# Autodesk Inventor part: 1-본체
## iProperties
Created: 2015-01
Part Number: 1-본체
Document SubType Name: Modeling
Designer: Administrator
Density: 2.71 g/cm^3
Material: 알루미늄-6061
Mass: 1021.13 g
Surface Area: 1059.8 cm^2
Volume: 376.8 cm^3
Author: Administrator
